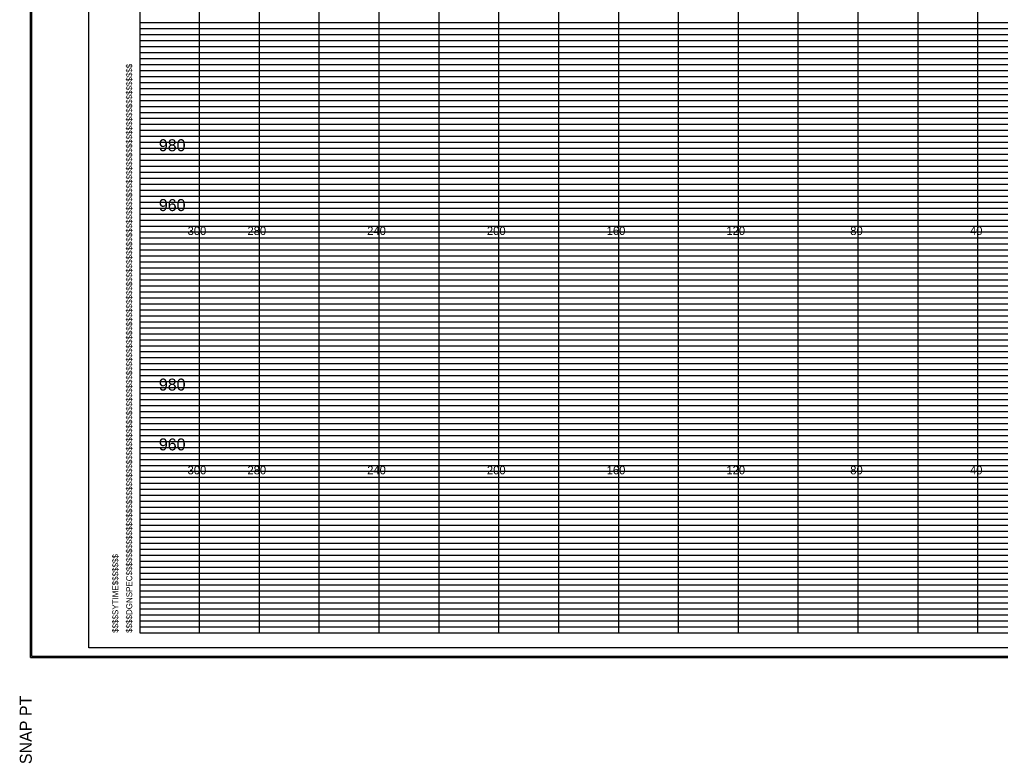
# Model space of a CAD drawing. Extents: x 2313580 to 2322968, y 282099 to 303247.
# Drawn here: x 2321588.4 to 2321916, y 287544 to 287792.7 of the extents above; entities that cross this region are included whole.
import ezdxf

# ---------------------------------------------------------------- set-up
doc = ezdxf.new("R2010")
doc.units = 0
for name, color, linetype in [('DESIGN - SHEET - Corner Text', 7, 'Continuous'), ('DESIGN - SHEET - Light Grid', 7, 'Continuous'), ('DESIGN - SHEET - Linework', 7, 'Continuous'), ('DESIGN - SHEET - Plot Shape', 7, 'Continuous'), ('DESIGN - TYPICAL - Text', 7, 'Continuous')]:
    doc.layers.add(name, color=color, linetype=linetype)

msp = doc.modelspace()

# ---------------------------------------------------------------- linework, layer by layer
at = {"layer": 'DESIGN - SHEET - Light Grid'}
for p, q in [((2321628.48, 287791.67), (2321788.48, 287791.67)), ((2321628.48, 287789.67), (2321788.48, 287789.67)), ((2321788.48, 287791.67), (2321948.48, 287791.67)), ((2321788.48, 287789.67), (2321948.48, 287789.67)), ((2321628.48, 287785.67), (2321788.48, 287785.67)), ((2321628.48, 287783.67), (2321788.48, 287783.67)), ((2321788.48, 287785.67), (2321948.48, 287785.67)), ((2321788.48, 287783.67), (2321948.48, 287783.67)), ((2321628.48, 287781.67), (2321788.48, 287781.67)), ((2321788.48, 287781.67), (2321948.48, 287781.67)), ((2321628.48, 287779.67), (2321788.48, 287779.67)), ((2321628.48, 287777.67), (2321788.48, 287777.67)), ((2321788.48, 287779.67), (2321948.48, 287779.67)), ((2321788.48, 287777.67), (2321948.48, 287777.67)), ((2321628.48, 287775.67), (2321788.48, 287775.67)), ((2321628.48, 287773.67), (2321788.48, 287773.67)), ((2321788.48, 287775.67), (2321948.48, 287775.67)), ((2321788.48, 287773.67), (2321948.48, 287773.67)), ((2321628.48, 287771.67), (2321788.48, 287771.67)), ((2321788.48, 287771.67), (2321948.48, 287771.67)), ((2321628.48, 287769.67), (2321788.48, 287769.67)), ((2321788.48, 287769.67), (2321948.48, 287769.67)), ((2321628.48, 287765.67), (2321788.48, 287765.67)), ((2321628.48, 287763.67), (2321788.48, 287763.67)), ((2321788.48, 287765.67), (2321948.48, 287765.67)), ((2321788.48, 287763.67), (2321948.48, 287763.67)), ((2321628.48, 287761.67), (2321788.48, 287761.67)), ((2321788.48, 287761.67), (2321948.48, 287761.67)), ((2321628.48, 287759.67), (2321788.48, 287759.67)), ((2321628.48, 287757.67), (2321788.48, 287757.67)), ((2321788.48, 287759.67), (2321948.48, 287759.67)), ((2321788.48, 287757.67), (2321948.48, 287757.67)), ((2321628.48, 287755.67), (2321788.48, 287755.67)), ((2321628.48, 287753.67), (2321788.48, 287753.67)), ((2321788.48, 287755.67), (2321948.48, 287755.67)), ((2321788.48, 287753.67), (2321948.48, 287753.67)), ((2321628.48, 287751.67), (2321788.48, 287751.67)), ((2321788.48, 287751.67), (2321948.48, 287751.67)), ((2321628.48, 287749.67), (2321788.48, 287749.67)), ((2321788.48, 287749.67), (2321948.48, 287749.67)), ((2321628.48, 287745.67), (2321788.48, 287745.67)), ((2321788.48, 287745.67), (2321948.48, 287745.67)), ((2321628.48, 287743.67), (2321788.48, 287743.67)), ((2321628.48, 287741.67), (2321788.48, 287741.67)), ((2321788.48, 287743.67), (2321948.48, 287743.67)), ((2321788.48, 287741.67), (2321948.48, 287741.67)), ((2321628.48, 287739.67), (2321788.48, 287739.67)), ((2321628.48, 287737.67), (2321788.48, 287737.67)), ((2321788.48, 287739.67), (2321948.48, 287739.67)), ((2321788.48, 287737.67), (2321948.48, 287737.67)), ((2321628.48, 287735.67), (2321788.48, 287735.67)), ((2321788.48, 287735.67), (2321948.48, 287735.67)), ((2321628.48, 287733.67), (2321788.48, 287733.67)), ((2321628.48, 287731.67), (2321788.48, 287731.67)), ((2321788.48, 287733.67), (2321948.48, 287733.67)), ((2321788.48, 287731.67), (2321948.48, 287731.67)), ((2321628.48, 287729.67), (2321788.48, 287729.67)), ((2321788.48, 287729.67), (2321948.48, 287729.67)), ((2321628.48, 287725.67), (2321788.48, 287725.67)), ((2321788.48, 287725.67), (2321948.48, 287725.67)), ((2321628.48, 287723.67), (2321788.48, 287723.67)), ((2321628.48, 287721.67), (2321788.48, 287721.67)), ((2321788.48, 287723.67), (2321948.48, 287723.67)), ((2321788.48, 287721.67), (2321948.48, 287721.67)), ((2321628.48, 287719.67), (2321788.48, 287719.67)), ((2321628.48, 287717.67), (2321788.48, 287717.67)), ((2321788.48, 287719.67), (2321948.48, 287719.67)), ((2321788.48, 287717.67), (2321948.48, 287717.67)), ((2321628.48, 287715.67), (2321788.48, 287715.67)), ((2321788.48, 287715.67), (2321948.48, 287715.67)), ((2321628.48, 287713.67), (2321788.48, 287713.67)), ((2321628.48, 287711.67), (2321788.48, 287711.67)), ((2321788.48, 287713.67), (2321948.48, 287713.67)), ((2321788.48, 287711.67), (2321948.48, 287711.67)), ((2321628.48, 287709.67), (2321788.48, 287709.67)), ((2321788.48, 287709.67), (2321948.48, 287709.67)), ((2321628.48, 287705.67), (2321788.48, 287705.67)), ((2321788.48, 287705.67), (2321948.48, 287705.67)), ((2321628.48, 287703.67), (2321788.48, 287703.67)), ((2321628.48, 287701.67), (2321788.48, 287701.67)), ((2321788.48, 287703.67), (2321948.48, 287703.67)), ((2321788.48, 287701.67), (2321948.48, 287701.67)), ((2321628.48, 287699.67), (2321788.48, 287699.67)), ((2321788.48, 287699.67), (2321948.48, 287699.67)), ((2321628.48, 287697.67), (2321788.48, 287697.67)), ((2321628.48, 287695.67), (2321788.48, 287695.67)), ((2321788.48, 287697.67), (2321948.48, 287697.67)), ((2321788.48, 287695.67), (2321948.48, 287695.67)), ((2321628.48, 287693.67), (2321788.48, 287693.67)), ((2321628.48, 287691.67), (2321788.48, 287691.67)), ((2321788.48, 287693.67), (2321948.48, 287693.67)), ((2321788.48, 287691.67), (2321948.48, 287691.67)), ((2321628.48, 287689.67), (2321788.48, 287689.67)), ((2321788.48, 287689.67), (2321948.48, 287689.67)), ((2321628.48, 287685.67), (2321788.48, 287685.67)), ((2321788.48, 287685.67), (2321948.48, 287685.67)), ((2321628.48, 287683.67), (2321788.48, 287683.67)), ((2321628.48, 287681.67), (2321788.48, 287681.67)), ((2321788.48, 287683.67), (2321948.48, 287683.67)), ((2321788.48, 287681.67), (2321948.48, 287681.67)), ((2321628.48, 287679.67), (2321788.48, 287679.67)), ((2321788.48, 287679.67), (2321948.48, 287679.67)), ((2321628.48, 287677.67), (2321788.48, 287677.67)), ((2321628.48, 287675.67), (2321788.48, 287675.67)), ((2321788.48, 287677.67), (2321948.48, 287677.67)), ((2321788.48, 287675.67), (2321948.48, 287675.67)), ((2321628.48, 287673.67), (2321788.48, 287673.67)), ((2321788.48, 287673.67), (2321948.48, 287673.67)), ((2321628.48, 287671.67), (2321788.48, 287671.67)), ((2321628.48, 287669.67), (2321788.48, 287669.67)), ((2321788.48, 287671.67), (2321948.48, 287671.67)), ((2321788.48, 287669.67), (2321948.48, 287669.67)), ((2321628.48, 287665.67), (2321788.48, 287665.67)), ((2321788.48, 287665.67), (2321948.48, 287665.67)), ((2321628.48, 287663.67), (2321788.48, 287663.67)), ((2321788.48, 287663.67), (2321948.48, 287663.67)), ((2321628.48, 287661.67), (2321788.48, 287661.67)), ((2321628.48, 287659.67), (2321788.48, 287659.67)), ((2321788.48, 287661.67), (2321948.48, 287661.67)), ((2321788.48, 287659.67), (2321948.48, 287659.67)), ((2321628.48, 287657.67), (2321788.48, 287657.67)), ((2321628.48, 287655.67), (2321788.48, 287655.67)), ((2321788.48, 287657.67), (2321948.48, 287657.67)), ((2321788.48, 287655.67), (2321948.48, 287655.67)), ((2321628.48, 287653.67), (2321788.48, 287653.67)), ((2321788.48, 287653.67), (2321948.48, 287653.67)), ((2321628.48, 287651.67), (2321788.48, 287651.67)), ((2321628.48, 287649.67), (2321788.48, 287649.67)), ((2321788.48, 287651.67), (2321948.48, 287651.67)), ((2321788.48, 287649.67), (2321948.48, 287649.67)), ((2321628.48, 287645.67), (2321788.48, 287645.67)), ((2321788.48, 287645.67), (2321948.48, 287645.67)), ((2321628.48, 287643.67), (2321788.48, 287643.67)), ((2321788.48, 287643.67), (2321948.48, 287643.67)), ((2321628.48, 287641.67), (2321788.48, 287641.67)), ((2321628.48, 287639.67), (2321788.48, 287639.67)), ((2321788.48, 287641.67), (2321948.48, 287641.67)), ((2321788.48, 287639.67), (2321948.48, 287639.67)), ((2321628.48, 287637.67), (2321788.48, 287637.67)), ((2321628.48, 287635.67), (2321788.48, 287635.67)), ((2321788.48, 287637.67), (2321948.48, 287637.67)), ((2321788.48, 287635.67), (2321948.48, 287635.67)), ((2321628.48, 287633.67), (2321788.48, 287633.67)), ((2321788.48, 287633.67), (2321948.48, 287633.67)), ((2321628.48, 287631.67), (2321788.48, 287631.67)), ((2321628.48, 287629.67), (2321788.48, 287629.67)), ((2321788.48, 287631.67), (2321948.48, 287631.67)), ((2321788.48, 287629.67), (2321948.48, 287629.67)), ((2321628.48, 287625.67), (2321788.48, 287625.67)), ((2321628.48, 287623.67), (2321788.48, 287623.67)), ((2321788.48, 287625.67), (2321948.48, 287625.67)), ((2321788.48, 287623.67), (2321948.48, 287623.67)), ((2321628.48, 287621.67), (2321788.48, 287621.67)), ((2321628.48, 287619.67), (2321788.48, 287619.67)), ((2321788.48, 287621.67), (2321948.48, 287621.67)), ((2321788.48, 287619.67), (2321948.48, 287619.67)), ((2321628.48, 287617.67), (2321788.48, 287617.67)), ((2321788.48, 287617.67), (2321948.48, 287617.67)), ((2321628.48, 287615.67), (2321788.48, 287615.67)), ((2321628.48, 287613.67), (2321788.48, 287613.67)), ((2321788.48, 287615.67), (2321948.48, 287615.67)), ((2321788.48, 287613.67), (2321948.48, 287613.67)), ((2321628.48, 287611.67), (2321788.48, 287611.67)), ((2321628.48, 287609.67), (2321788.48, 287609.67)), ((2321788.48, 287611.67), (2321948.48, 287611.67)), ((2321788.48, 287609.67), (2321948.48, 287609.67)), ((2321628.48, 287605.67), (2321788.48, 287605.67)), ((2321628.48, 287603.67), (2321788.48, 287603.67)), ((2321788.48, 287605.67), (2321948.48, 287605.67)), ((2321788.48, 287603.67), (2321948.48, 287603.67)), ((2321628.48, 287601.67), (2321788.48, 287601.67)), ((2321628.48, 287599.67), (2321788.48, 287599.67)), ((2321788.48, 287601.67), (2321948.48, 287601.67)), ((2321788.48, 287599.67), (2321948.48, 287599.67)), ((2321628.48, 287597.67), (2321788.48, 287597.67)), ((2321788.48, 287597.67), (2321948.48, 287597.67)), ((2321628.48, 287595.67), (2321788.48, 287595.67)), ((2321628.48, 287593.67), (2321788.48, 287593.67)), ((2321788.48, 287595.67), (2321948.48, 287595.67)), ((2321788.48, 287593.67), (2321948.48, 287593.67)), ((2321628.48, 287591.67), (2321788.48, 287591.67)), ((2321788.48, 287591.67), (2321948.48, 287591.67)), ((2321628.48, 287589.67), (2321788.48, 287589.67)), ((2321788.48, 287589.67), (2321948.48, 287589.67))]:
    msp.add_line(p, q, dxfattribs=at)
at = {"layer": 'DESIGN - SHEET - Linework'}
for p, q in [((2321592.02, 287579.39), (2321592.02, 288015.95)), ((2321648.48, 287587.67), (2321648.48, 288007.67)), ((2321668.48, 287587.67), (2321668.48, 288007.67)), ((2321688.48, 287587.67), (2321688.48, 288007.67)), ((2321708.48, 287587.67), (2321708.48, 288007.67)), ((2321728.48, 287587.67), (2321728.48, 288007.67)), ((2321748.48, 287587.67), (2321748.48, 288007.67)), ((2321768.48, 287587.67), (2321768.48, 288007.67)), ((2321788.48, 287587.67), (2321788.48, 288007.67)), ((2321808.48, 287587.67), (2321808.48, 288007.67)), ((2321828.48, 287587.67), (2321828.48, 288007.67)), ((2321848.48, 287587.67), (2321848.48, 288007.67)), ((2321868.48, 287587.67), (2321868.48, 288007.67)), ((2321888.48, 287587.67), (2321888.48, 288007.67)), ((2321908.48, 287587.67), (2321908.48, 288007.67)), ((2321628.48, 287787.67), (2322268.48, 287787.67)), ((2321628.48, 287767.67), (2322268.48, 287767.67)), ((2321628.48, 287747.67), (2322268.48, 287747.67)), ((2321628.48, 287727.67), (2322268.48, 287727.67)), ((2321628.48, 287707.67), (2322268.48, 287707.67)), ((2321628.48, 287687.67), (2322268.48, 287687.67)), ((2321628.48, 287667.67), (2322268.48, 287667.67)), ((2321628.48, 287647.67), (2322268.48, 287647.67)), ((2321628.48, 287627.67), (2322268.48, 287627.67)), ((2321628.48, 287607.67), (2322268.48, 287607.67)), ((2321592.02, 287579.39), (2322272.82, 287579.39))]:
    msp.add_line(p, q, dxfattribs=at)
msp.add_lwpolyline([(2321628.48, 288007.67), (2321628.48, 287587.67), (2322268.48, 287587.67), (2322268.48, 288007.67), (2321628.48, 288007.67)], dxfattribs=at)
at = {"layer": 'DESIGN - SHEET - Plot Shape'}
for points in [[(2321592.42, 288015.55), (2322272.42, 288015.55), (2322272.42, 287579.79), (2321592.42, 287579.79)], [(2321611.48, 288007.67), (2322268.48, 288007.67), (2322268.48, 287582.67), (2321611.48, 287582.67)]]:
    msp.add_lwpolyline(points, close=True, dxfattribs=at)

# ---------------------------------------------------------------- texts
at = {"layer": 'DESIGN - SHEET - Corner Text'}
for s, height, p in [('$$$$DGNSPEC$$$$$$$$$$$$$$$$$$$$$$$$$$$$$$$$$$$$$$$$$$$$$$$$$$$$$$$$$$$$$$$$$$$$$$$$$$$$$$$$$$$$$$$$$$$$$$$$$$$$$$$$$$$$$$$$$$$', 2.00004, (2321625.96, 287587.67)), ('$$$$SYTIME$$$$$$$', 2, (2321621.32, 287587.67)), ('SNAP PT  ', 4, (2321592.42, 287543.79))]:
    msp.add_text(s, height=height, rotation=90, dxfattribs=at).set_placement(p)
at = {"layer": 'DESIGN - SHEET - Linework'}
for p in [(2321648.48, 287727.67), (2321648.48, 287647.67)]:
    msp.add_text('-', height=0.0001, dxfattribs=at).set_placement(p)
at = {"layer": 'DESIGN - TYPICAL - Text'}
for s, height, p in [('980', 4, (2321634.86, 287748.67)), ('960', 4, (2321634.86, 287728.67)), ('-300', 2.8, (2321643.22, 287720.67)), ('-280', 2.8, (2321663.22, 287720.67)), ('-240', 2.8, (2321703.22, 287720.67)), ('-200', 2.8, (2321743.22, 287720.67)), ('-160', 2.8, (2321783.22, 287720.67)), ('-120', 2.8, (2321823.22, 287720.67)), ('-80', 2.8, (2321864.59, 287720.67)), ('-40', 2.8, (2321904.59, 287720.67)), ('980', 4, (2321634.86, 287668.67)), ('960', 4, (2321634.86, 287648.67)), ('-300', 2.8, (2321643.22, 287640.67)), ('-280', 2.8, (2321663.22, 287640.67)), ('-240', 2.8, (2321703.22, 287640.67)), ('-200', 2.8, (2321743.22, 287640.67)), ('-160', 2.8, (2321783.22, 287640.67)), ('-120', 2.8, (2321823.22, 287640.67)), ('-80', 2.8, (2321864.59, 287640.67)), ('-40', 2.8, (2321904.59, 287640.67))]:
    msp.add_text(s, height=height, dxfattribs=at).set_placement(p)

doc.saveas('drawing.dxf')
